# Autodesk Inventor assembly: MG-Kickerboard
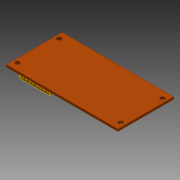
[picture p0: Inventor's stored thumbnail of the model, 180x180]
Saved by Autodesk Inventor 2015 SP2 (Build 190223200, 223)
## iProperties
Created: 2015-08
Part Number: MG-Kickerboard
Document SubType Name: Assembly
Designer: rYan
Author: rYan
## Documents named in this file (3)
- D:\Tigers SVN\mechanik\2016\Inventor\Elektronik\MG-Kickerboard.iam
- D:\Tigers SVN\mechanik\2016\Inventor\Elektronik\Kickerboard.ipt
- D:\Tigers SVN\mechanik\2016\Inventor\Kaufteile\Micromatch F16.ipt
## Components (2 placed, 2 different names)
1. Kickerboard:1 — Fluchtend:1, Passend:1, Fluchtend:2
2. Micromatch F16:1 — Fluchtend:1, Passend:1, Fluchtend:2
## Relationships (3: Flush 2, Mate 1)
- Fluchtend:1 [Flush]: Kickerboard:1 ↔ Micromatch F16:1
- Passend:1 [Mate]: Kickerboard:1 ↔ Micromatch F16:1
- Fluchtend:2 [Flush]: Kickerboard:1 ↔ Micromatch F16:1
